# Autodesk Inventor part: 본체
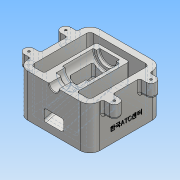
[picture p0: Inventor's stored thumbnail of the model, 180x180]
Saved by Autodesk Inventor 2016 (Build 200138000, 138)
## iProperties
Created: 2018-01
Part Number: 본체
Material: 알루미늄 6061
Document SubType Name: Modeling
Designer: Administrator
Density: 2.7 g/cm^3
Appearance: 알루미늄 - 평지
Mass: 995.217 g
Surface Area: 834.407 cm^2
Volume: 368.599 cm^3
Author: Administrator
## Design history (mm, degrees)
sketch "스케치1"
  geometry: L1 (55, -55)-(-55, -55); L2 (-55, -55)-(-55, 55); L3 (-55, 55)-(55, 55); L4 (55, 55)-(55, -55); L5 (55, -55)-(-55, 55); L6 (-55, -55)-(55, 55); 1 further point
  constraints: 12 end point, 2 midpoint, 2 parallel, 1 horizontal, 1 perpendicular
  dimensions: "d0" = 110 distance of L2.end L3.end; "d1" = 110 distance of L1.end L2.end
extrude "돌출1" new body sketch "스케치1" distance "d2" = 65; taper "d3" = 0 deg
sketch "스케치2"
  geometry: L1 (-55, -55)-(55, -55) reference; L2 (-55, 55)-(-55, -55) reference; L3 (-65, -20.5)-(-55, -20.5); L4 (-55, -20.5)-(-55, -35.5); L5 (-55, -35.5)-(-65, -35.5); L6 (-65, -35.5)-(-65, -20.5); A1 r 7.5 centre (-65, -28) between (-65, -20.5) and (-65, -35.5); 2 further points
  constraints: 8 end point, 2 midpoint, 2 parallel, 2 point on circle, 1 centre point, 1 horizontal, 1 perpendicular, 1 point on line
  dimensions: "d4" = 10 distance of L4.end L5.end; "d5" = 7.5 radius of A1; "d6" = 27 distance from line of L1 A1.centre
extrude "돌출2" join sketch "스케치2" distance "d7" = 20; taper "d8" = 0 deg
feature "쉘1" dims "d12" = 10
sketch "스케치3"
  geometry: L1 (-45, 0)-(-45, 65) reference; L2 (-45, 8.564)-(35, 30); L3 (35, 30)-(35, 65); L4 (-45, 65)-(45, 65) reference; L5 (45, 0)-(-45, 0) reference; L6 (55, 0)-(55, 65) reference; 1 further point
  constraints: 4 end point, 2 point on line, 1 parallel
  dimensions: "d13" = 30 distance from line of L5 L2.end; "d14" = 20 distance between parallel lines of L6 L3; "d15" = 105 deg angle of L1 L2
extrude "돌출3" join sketch "스케치3" stored distance "d16" = 50; taper "d17" = 0 deg
sketch "스케치6"
  geometry: L1 (-55, 0)-(-55, 65) reference; L2 (-55, 65)-(30, 65); L3 (-45, 65)-(35, 65) reference; L4 (-35.5, 65)-(-55, 65) reference; L5 (-55, 65)-(-55, 57.5); L6 (-55, 57.5)-(-36, 57.5); L7 (-36, 57.5)-(-36, 49); L8 (-36, 49)-(-22, 49); L9 (-22, 49)-(-22, 45); L10 (-22, 45)-(25, 45); L11 (25, 45)-(25, 50); L12 (25, 50)-(30, 50); L13 (30, 50)-(30, 65); 1 further point
  constraints: 20 end point, 6 perpendicular, 2 horizontal, 2 point on line
  dimensions: "d25" = 15 diameter of L6 L2; "d26" = 32 diameter of L8 L2; "d27" = 40 diameter of L10 L2; "d28" = 30 diameter of L12 L2; "d29" = 5 distance between parallel lines of L13 L11; "d30" = 47 distance of L9.end L10.end; "d31" = 14 distance of L7.end L8.end; "d32" = 19 distance of L5.end L6.end
revolve "회전1" sketch "스케치6" stored, may be unused: angle "d33" = 90 deg
sketch "스케치8"
  geometry: L1 (-55, 11.061)-(20, 31.157); L2 (20, 31.157)-(20, 58.854); L3 (-55, 0)-(-55, 65) reference; L4 (20, 58.854)-(-17, 58.854); L5 (-17, 58.854)-(-17, 39.243); L6 (-17, 39.243)-(-55, 29.061); L7 (35, 30)-(-45, 8.564) reference; L8 (-22, 49)-(-22, 65) reference; 1 further point
  constraints: 10 end point, 3 parallel, 2 perpendicular, 2 point on line
  dimensions: "d35" = 5 distance between parallel lines of L7 L1; "d36" = 18 distance of L1.start L6.end; "d37" = 37 distance between parallel lines of L2 L5; "d38" = 5 distance between parallel lines of L5 L8
extrude "돌출5" cut sketch "스케치8" stored distance "d39" = 30; taper "d40" = 0 deg
hole "구멍1" diameter "d43" = 3.242; stored, may be unused: countersink angle "d47" = 90 deg, drill point angle "d49" = 118 deg; dims "d44" = 9, "d45" = 4, "d46" = 2, "d48" = 11, "d79" = 10, "d80" = 10
fillet "모깎기1" dims "d53" = 15
fillet "모깎기2" dims "d54" = 1
fillet "모깎기3" dims "d55" = 5
fillet "모깎기4" dims "d56" = 3
fillet "모깎기6" dims "d58" = 3
chamfer "모따기1" distance "d63" = 1; stored, may be unused: second distance "d64" = 2, angle "d65" = 45 deg
fillet "모깎기11" dims "d66" = 3
sketch "스케치9"
  geometry: L1 (0, 80)-(0, 0) reference; L2 (-65, -15)-(0, -15) reference; 2 further points
  constraints: 1 other
  dimensions: "d67" = 20 distance from line of L1 point (-20, 40); "d68" = 55 distance from line of L2 point (-20, 40)
feature "엠보싱1" sketch "스케치9" dims "d0" = 110, "d1" = 110, "d9" = 20, "d69" = 0.5, "d70" = 0
fillet "모깎기13" dims "d72" = 3
fillet "모깎기14" dims "d73" = 3
chamfer "모따기2" distance "d74" = 1; stored, may be unused: second distance "d75" = 2, angle "d76" = 45 deg
node "솔리드1"
pattern_linear "직사각형 패턴1" dims "d11" = 56
mirror "대칭1"
pattern_linear "직사각형 패턴2" dims "d52" = 56
mirror "대칭2"
